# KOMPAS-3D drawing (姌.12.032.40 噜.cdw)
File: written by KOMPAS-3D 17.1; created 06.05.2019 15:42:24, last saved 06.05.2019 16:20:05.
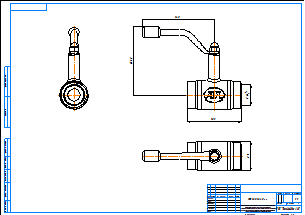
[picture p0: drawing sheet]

Sheet 1: A2, landscape

Title block, sheet 1: name: КШ.12.032.40 рр; material: Внимание! Данный продукт является объектом авторского права ООО «Торговый Дом АДЛ». / Запрещается изменение, копирование, распространение / (в том числе путем копирования на другие сайты и ресурсы в Интернете) / или любое иное использование информации и объектов без предварительного / согласия правообладателя (ООО «Торговый Дом АДЛ»).; scale: 1:1; sheets: 1; organisation: ООО "Торговый дом АДЛ"; sheet format: A2; stored path: C:\Users\tra\Desktop\2д чертежи\Шаровые краны БИВАЛ\КШ_Бивал_серия_11_12\KOMPAS_2D\КШ.12.032.40 рр.cdw

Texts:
  user
Dimensions and other numbers on the sheet: 105; 133,1; 140; 57; 1:1; 1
